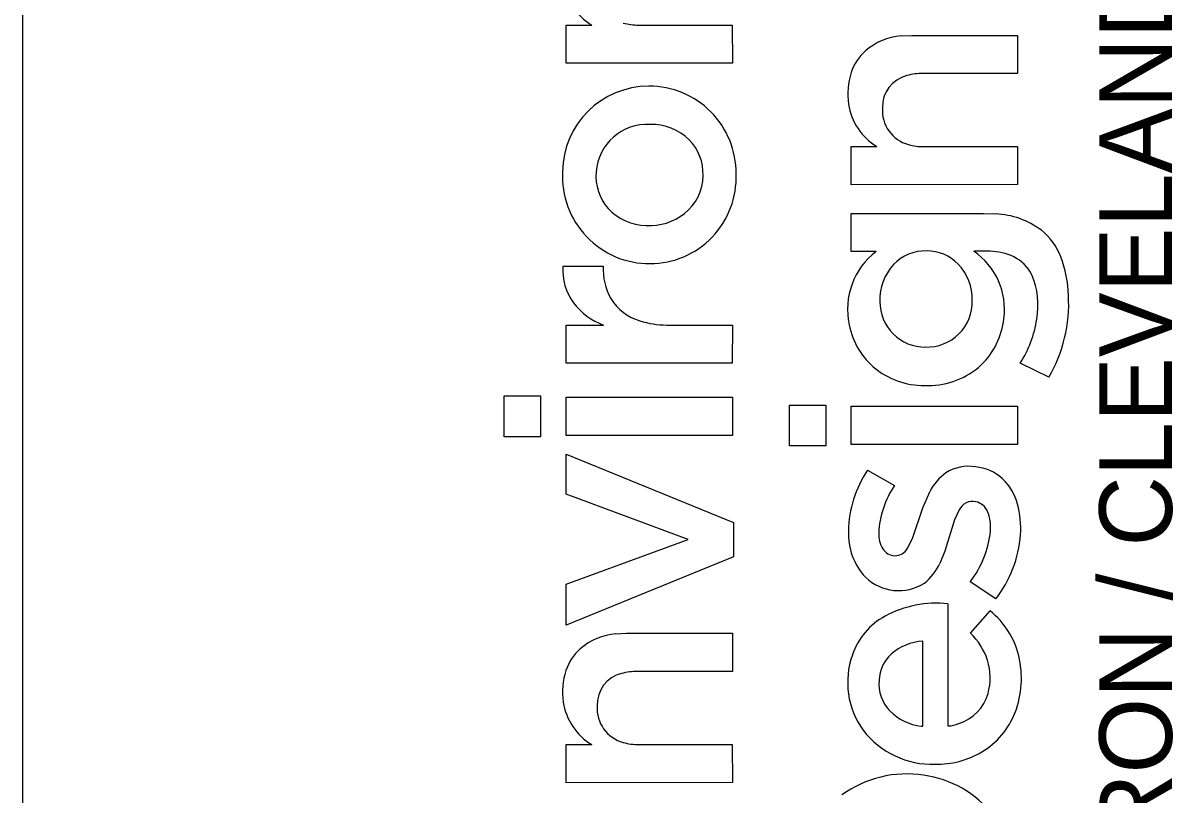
# Model space of a CAD drawing. Extents: x 0 to 34, y -1.2 to 22.
# Drawn here: x 32 to 32.901, y 3.278 to 3.882 of the extents above; entities that cross this region are included whole.
import ezdxf

# ---------------------------------------------------------------- set-up
doc = ezdxf.new("R2010")
doc.units = 0
doc.layers.add('SH_Border', color=7, linetype='Continuous')
doc.layers.add('SH_Data', color=7, linetype='Continuous')

msp = doc.modelspace()

# ---------------------------------------------------------------- linework, layer by layer
at = {"layer": 'SH_Border'}
msp.add_line((32, 0.5), (32, 21.5), dxfattribs=at)
at = {"layer": 'SH_Data'}
for p, q in [((32.42542, 3.88066), (32.44552, 3.88071)), ((32.42542, 3.85086), (32.42542, 3.88066)), ((32.48222, 3.88071), (32.55569, 3.88071)), ((32.55569, 3.88071), (32.55571, 3.85096)), ((32.68784, 3.8722), (32.69634, 3.87266)), ((32.69634, 3.87266), (32.77916, 3.87266)), ((32.77916, 3.87266), (32.77917, 3.84287)), ((32.55571, 3.85096), (32.42542, 3.85086)), ((32.77917, 3.84287), (32.70485, 3.8428)), ((32.64888, 3.7855), (32.66897, 3.78555)), ((32.64888, 3.75569), (32.64888, 3.7855)), ((32.70568, 3.78555), (32.77915, 3.78555)), ((32.77915, 3.78555), (32.77917, 3.75579)), ((32.77917, 3.75579), (32.64888, 3.75569)), ((32.6489, 3.70336), (32.64889, 3.73322)), ((32.64889, 3.73322), (32.75236, 3.73322)), ((32.75236, 3.73322), (32.76191, 3.73285)), ((32.66836, 3.70336), (32.6489, 3.70336)), ((32.75763, 3.70356), (32.74487, 3.70361)), ((32.42299, 3.69193), (32.45454, 3.69193)), ((32.42542, 3.64577), (32.45473, 3.64579)), ((32.42542, 3.61593), (32.42542, 3.64577)), ((32.50413, 3.64581), (32.55571, 3.64573)), ((32.55571, 3.64573), (32.55565, 3.61593)), ((32.55565, 3.61593), (32.42542, 3.61593)), ((32.8036, 3.60491), (32.7812, 3.61598)), ((32.37705, 3.55818), (32.37705, 3.59026)), ((32.37705, 3.59026), (32.40543, 3.59026)), ((32.40543, 3.59026), (32.40543, 3.55818)), ((32.42542, 3.55942), (32.42542, 3.58928)), ((32.42542, 3.58928), (32.55571, 3.58928)), ((32.55571, 3.58928), (32.55571, 3.55942)), ((32.60051, 3.55111), (32.60051, 3.58319)), ((32.60051, 3.58319), (32.62889, 3.58319)), ((32.62889, 3.58319), (32.62889, 3.55111)), ((32.64888, 3.55234), (32.64888, 3.5822)), ((32.64888, 3.5822), (32.77917, 3.5822)), ((32.77917, 3.5822), (32.77917, 3.55234)), ((32.55571, 3.55942), (32.42542, 3.55942)), ((32.40543, 3.55818), (32.37705, 3.55818)), ((32.62889, 3.55111), (32.60051, 3.55111)), ((32.77917, 3.55234), (32.64888, 3.55234)), ((32.42542, 3.51327), (32.42542, 3.5446)), ((32.42542, 3.5446), (32.5567, 3.4913)), ((32.66151, 3.53207), (32.68268, 3.52025)), ((32.70483, 3.50258), (32.71036, 3.51526)), ((32.52117, 3.47798), (32.42542, 3.51327)), ((32.69675, 3.47868), (32.70483, 3.50258)), ((32.73342, 3.50101), (32.72985, 3.4933)), ((32.5567, 3.4913), (32.5567, 3.46441)), ((32.72985, 3.4933), (32.72213, 3.46882)), ((32.42542, 3.44294), (32.52117, 3.47798)), ((32.69299, 3.47117), (32.69675, 3.47868)), ((32.72213, 3.46882), (32.71822, 3.45921)), ((32.5567, 3.46441), (32.42542, 3.41086)), ((32.42542, 3.41086), (32.42542, 3.44294)), ((32.76214, 3.43141), (32.74198, 3.44469)), ((32.72453, 3.42747), (32.72463, 3.33195)), ((32.74228, 3.40465), (32.75768, 3.422)), ((32.46439, 3.40397), (32.47289, 3.40443)), ((32.47289, 3.40443), (32.55571, 3.40443)), ((32.55571, 3.40443), (32.55571, 3.37465)), ((32.70489, 3.33182), (32.70489, 3.39834)), ((32.55571, 3.37465), (32.4814, 3.37457)), ((32.70361, 3.33165), (32.70489, 3.33182)), ((32.42542, 3.31728), (32.44552, 3.31733)), ((32.42542, 3.28747), (32.42542, 3.31728)), ((32.48222, 3.31733), (32.55569, 3.31733)), ((32.55569, 3.31733), (32.55571, 3.28756)), ((32.55571, 3.28756), (32.42542, 3.28747))]:
    msp.add_line(p, q, dxfattribs=at)
for points in [[(32.42542, 3.85086), (32.42542, 3.88066), (32.44552, 3.88071)], [(32.48222, 3.88071), (32.55569, 3.88071), (32.55571, 3.85096), (32.42542, 3.85086)], [(32.68784, 3.8722), (32.69634, 3.87266), (32.77916, 3.87266), (32.77917, 3.84287), (32.70485, 3.8428)], [(32.64888, 3.75569), (32.64888, 3.7855), (32.66897, 3.78555)], [(32.70568, 3.78555), (32.77915, 3.78555), (32.77917, 3.75579), (32.64888, 3.75569)], [(32.66836, 3.70336), (32.6489, 3.70336), (32.64889, 3.73322), (32.75236, 3.73322), (32.76191, 3.73285)], [(32.75763, 3.70356), (32.74487, 3.70361)], [(32.42299, 3.69193), (32.45454, 3.69193)], [(32.50413, 3.64581), (32.55571, 3.64573), (32.55565, 3.61593), (32.42542, 3.61593)], [(32.42542, 3.61593), (32.42542, 3.64577), (32.45473, 3.64579)], [(32.8036, 3.60491), (32.7812, 3.61598)], [(32.66151, 3.53207), (32.68268, 3.52025)], [(32.69299, 3.47117), (32.69675, 3.47868), (32.70483, 3.50258), (32.71036, 3.51526)], [(32.73342, 3.50101), (32.72985, 3.4933), (32.72213, 3.46882), (32.71822, 3.45921)], [(32.76214, 3.43141), (32.74198, 3.44469)], [(32.72453, 3.42747), (32.72463, 3.33195)], [(32.74228, 3.40465), (32.75768, 3.422)], [(32.46439, 3.40397), (32.47289, 3.40443), (32.55571, 3.40443), (32.55571, 3.37465), (32.4814, 3.37457)], [(32.70361, 3.33165), (32.70489, 3.33182), (32.70489, 3.39834)], [(32.42542, 3.28747), (32.42542, 3.31728), (32.44552, 3.31733)], [(32.48222, 3.31733), (32.55569, 3.31733), (32.55571, 3.28756), (32.42542, 3.28747)]]:
    msp.add_lwpolyline(points, dxfattribs=at)
for points in [[(32.37705, 3.55818), (32.37705, 3.59026), (32.40543, 3.59026), (32.40543, 3.55818)], [(32.42542, 3.55942), (32.42542, 3.58928), (32.55571, 3.58928), (32.55571, 3.55942)], [(32.60051, 3.55111), (32.60051, 3.58319), (32.62889, 3.58319), (32.62889, 3.55111)], [(32.64888, 3.55234), (32.64888, 3.5822), (32.77917, 3.5822), (32.77917, 3.55234)], [(32.42542, 3.41086), (32.42542, 3.44294), (32.52117, 3.47798), (32.42542, 3.51327), (32.42542, 3.5446), (32.5567, 3.4913), (32.5567, 3.46441)]]:
    msp.add_lwpolyline(points, close=True, dxfattribs=at)
for centre, radius, start, end in [((32.47027, 3.92141), 0.04763, 188.96462, 238.69865), ((32.47027, 3.92141), 0.04763, 188.96462, 238.69865), ((32.48183, 3.92286), 0.04215, 254.08913, 270.52838), ((32.48183, 3.92286), 0.04215, 254.08913, 270.52838), ((32.69216, 3.82251), 0.04988, 94.97056, 130.22484), ((32.69216, 3.82251), 0.04988, 94.97056, 130.22484), ((32.68694, 3.83085), 0.04016, 132.22383, 161.68229), ((32.68694, 3.83085), 0.04016, 132.22383, 161.68229), ((32.70217, 3.82642), 0.05602, 162.27398, 187.79173), ((32.70217, 3.82642), 0.05602, 162.27398, 187.79173), ((32.69828, 3.81689), 0.02498, 103.68683, 182.21395), ((32.69828, 3.81689), 0.02498, 103.68683, 182.21395), ((32.70453, 3.79679), 0.04601, 89.60515, 105.33026), ((32.70453, 3.79679), 0.04601, 89.60515, 105.33026), ((32.49014, 3.76543), 0.0674, 89.84756, 179.64047), ((32.49014, 3.76543), 0.0674, 89.84756, 179.64047), ((32.49057, 3.76474), 0.0681, 359.54009, 90.21138), ((32.49057, 3.76474), 0.0681, 359.54009, 90.21138), ((32.69372, 3.82624), 0.04763, 188.96462, 238.69865), ((32.69372, 3.82624), 0.04763, 188.96462, 238.69865), ((32.7008, 3.81381), 0.02757, 175.58441, 255.13816), ((32.7008, 3.81381), 0.02757, 175.58441, 255.13816), ((32.48923, 3.76263), 0.0404, 87.04809, 175.57259), ((32.48923, 3.76263), 0.0404, 87.04809, 175.57259), ((32.49204, 3.75999), 0.04299, 45.84264, 90.98008), ((32.49204, 3.75999), 0.04299, 45.84264, 90.98008), ((32.49458, 3.76421), 0.03821, 357.88569, 44.15902), ((32.49458, 3.76421), 0.03821, 357.88569, 44.15902), ((32.70529, 3.82769), 0.04215, 254.08913, 270.52838), ((32.70529, 3.82769), 0.04215, 254.08913, 270.52838), ((32.49083, 3.76209), 0.06819, 176.8344, 270.40384), ((32.49083, 3.76209), 0.06819, 176.8344, 270.40384), ((32.48729, 3.7625), 0.03848, 175.15378, 221.14706), ((32.48729, 3.7625), 0.03848, 175.15378, 221.14706), ((32.49123, 3.76139), 0.06749, 270.06243, 2.37759), ((32.49123, 3.76139), 0.06749, 270.06243, 2.37759), ((32.49446, 3.76318), 0.0383, 308.28936, 359.43468), ((32.49446, 3.76318), 0.0383, 308.28936, 359.43468), ((32.48919, 3.76607), 0.04228, 223.09994, 268.80895), ((32.48919, 3.76607), 0.04228, 223.09994, 268.80895), ((32.49096, 3.7679), 0.04418, 266.56515, 308.06078), ((32.49096, 3.7679), 0.04418, 266.56515, 308.06078), ((32.75907, 3.66789), 0.06503, 53.40344, 87.49062), ((32.75907, 3.66789), 0.06503, 53.40344, 87.49062), ((32.76517, 3.68039), 0.05141, 21.60748, 50.5577), ((32.76517, 3.68039), 0.05141, 21.60748, 50.5577), ((32.70292, 3.65813), 0.05692, 127.37482, 192.22468), ((32.70292, 3.65813), 0.05692, 127.37482, 192.22468), ((32.70693, 3.66927), 0.0346, 88.47302, 136.42562), ((32.70693, 3.66927), 0.0346, 88.47302, 136.42562), ((32.70814, 3.66963), 0.03424, 44.27195, 90.47623), ((32.70814, 3.66963), 0.03424, 44.27195, 90.47623), ((32.71421, 3.65829), 0.05472, 352.1125, 55.92295), ((32.71421, 3.65829), 0.05472, 352.1125, 55.92295), ((32.75666, 3.65725), 0.04633, 65.01687, 88.8011), ((32.75666, 3.65725), 0.04633, 65.01687, 88.8011), ((32.7626, 3.67155), 0.03085, 26.26808, 63.80301), ((32.7626, 3.67155), 0.03085, 26.26808, 63.80301), ((32.73069, 3.66714), 0.08835, 1.15143, 21.3627), ((32.73069, 3.66714), 0.08835, 1.15143, 21.3627), ((32.46616, 3.68882), 0.04329, 175.87313, 216.34747), ((32.46616, 3.68882), 0.04329, 175.87313, 216.34747), ((32.50087, 3.68948), 0.04639, 176.9688, 209.60636), ((32.50087, 3.68948), 0.04639, 176.9688, 209.60636), ((32.71141, 3.66602), 0.0401, 137.46739, 182.33237), ((32.71141, 3.66602), 0.0401, 137.46739, 182.33237), ((32.70368, 3.666), 0.03996, 358.57141, 43.53765), ((32.70368, 3.666), 0.03996, 358.57141, 43.53765), ((32.73565, 3.66154), 0.05953, 349.30734, 23.43071), ((32.73565, 3.66154), 0.05953, 349.30734, 23.43071), ((32.70538, 3.66244), 0.11383, 329.6388, 3.25998), ((32.70538, 3.66244), 0.11383, 329.6388, 3.25998), ((32.47466, 3.69716), 0.05511, 218.09809, 248.7907), ((32.47466, 3.69716), 0.05511, 218.09809, 248.7907), ((32.49514, 3.68814), 0.04079, 211.94466, 253.2028), ((32.49514, 3.68814), 0.04079, 211.94466, 253.2028), ((32.70645, 3.6637), 0.03511, 178.88208, 271.08374), ((32.70645, 3.6637), 0.03511, 178.88208, 271.08374), ((32.70818, 3.66404), 0.03546, 268.27882, 1.55016), ((32.70818, 3.66404), 0.03546, 268.27882, 1.55016), ((32.50465, 3.7165), 0.07069, 252.46555, 269.57296), ((32.50465, 3.7165), 0.07069, 252.46555, 269.57296), ((32.70988, 3.65708), 0.05887, 313.74196, 353.8554), ((32.70988, 3.65708), 0.05887, 313.74196, 353.8554), ((32.70738, 3.66334), 0.08771, 327.31495, 351.57478), ((32.70738, 3.66334), 0.08771, 327.31495, 351.57478), ((32.70463, 3.65696), 0.05837, 190.75182, 231.28919), ((32.70463, 3.65696), 0.05837, 190.75182, 231.28919), ((32.70954, 3.65901), 0.06051, 269.6361, 312.70877), ((32.70954, 3.65901), 0.06051, 269.6361, 312.70877), ((32.70632, 3.66112), 0.06269, 232.46061, 272.59022), ((32.70632, 3.66112), 0.06269, 232.46061, 272.59022), ((32.73636, 3.48258), 0.08973, 146.53104, 178.7571), ((32.73636, 3.48258), 0.08973, 146.53104, 178.7571), ((32.7406, 3.5026), 0.03263, 80.17192, 122.51969), ((32.7406, 3.5026), 0.03263, 80.17192, 122.51969), ((32.74278, 3.49824), 0.03667, 47.79344, 84.68918), ((32.74278, 3.49824), 0.03667, 47.79344, 84.68918), ((32.74661, 3.49713), 0.04053, 125.51182, 153.41595), ((32.74661, 3.49713), 0.04053, 125.51182, 153.41595), ((32.73788, 3.4946), 0.04267, 14.9966, 46.20632), ((32.73788, 3.4946), 0.04267, 14.9966, 46.20632), ((32.74519, 3.4789), 0.07495, 146.51121, 176.91007), ((32.74519, 3.4789), 0.07495, 146.51121, 176.91007), ((32.74384, 3.49631), 0.01143, 76.66094, 155.7053), ((32.74384, 3.49631), 0.01143, 76.66094, 155.7053), ((32.74397, 3.49511), 0.01256, 21.5098, 78.52618), ((32.74397, 3.49511), 0.01256, 21.5098, 78.52618), ((32.71044, 3.48674), 0.07121, 355.83062, 15.39138), ((32.71044, 3.48674), 0.07121, 355.83062, 15.39138), ((32.72592, 3.48766), 0.03209, 354.57264, 22.06805), ((32.72592, 3.48766), 0.03209, 354.57264, 22.06805), ((32.69666, 3.48238), 0.05005, 177.53659, 222.79318), ((32.69666, 3.48238), 0.05005, 177.53659, 222.79318), ((32.6931, 3.48233), 0.02276, 178.47474, 211.08679), ((32.6931, 3.48233), 0.02276, 178.47474, 211.08679), ((32.68248, 3.49149), 0.0757, 321.81101, 354.79685), ((32.68248, 3.49149), 0.0757, 321.81101, 354.79685), ((32.68952, 3.4882), 0.09219, 321.9777, 355.87384), ((32.68952, 3.4882), 0.09219, 321.9777, 355.87384), ((32.68331, 3.4767), 0.01148, 212.23676, 268.37769), ((32.68331, 3.4767), 0.01148, 212.23676, 268.37769), ((32.68342, 3.47589), 0.01067, 267.71603, 333.73375), ((32.68342, 3.47589), 0.01067, 267.71603, 333.73375), ((32.68098, 3.4758), 0.04077, 308.08772, 335.98736), ((32.68098, 3.4758), 0.04077, 308.08772, 335.98736), ((32.68599, 3.47535), 0.0375, 225.98539, 302.47965), ((32.68599, 3.47535), 0.0375, 225.98539, 302.47965), ((32.7152, 3.34414), 0.08384, 83.61499, 118.28755), ((32.7152, 3.34414), 0.08384, 83.61499, 118.28755), ((32.70239, 3.36906), 0.05583, 118.83082, 160.62438), ((32.70239, 3.36906), 0.05583, 118.83082, 160.62438), ((32.71744, 3.37167), 0.06443, 13.53365, 51.36148), ((32.71744, 3.37167), 0.06443, 13.53365, 51.36148), ((32.46871, 3.35428), 0.04988, 94.96958, 130.22249), ((32.46871, 3.35428), 0.04988, 94.96958, 130.22249), ((32.70785, 3.35609), 0.04235, 94.00805, 130.88169), ((32.70785, 3.35609), 0.04235, 94.00805, 130.88169), ((32.70378, 3.36556), 0.05486, 19.03571, 45.44059), ((32.70378, 3.36556), 0.05486, 19.03571, 45.44059), ((32.46348, 3.36263), 0.04015, 132.22192, 161.68183), ((32.46348, 3.36263), 0.04015, 132.22192, 161.68183), ((32.71041, 3.36612), 0.06437, 160.52012, 215.78311), ((32.71041, 3.36612), 0.06437, 160.52012, 215.78311), ((32.70048, 3.36628), 0.02985, 132.98507, 177.179), ((32.70048, 3.36628), 0.02985, 132.98507, 177.179), ((32.71069, 3.3697), 0.047, 344.60586, 17.007), ((32.71069, 3.3697), 0.047, 344.60586, 17.007), ((32.70635, 3.36921), 0.07579, 339.3542, 13.37853), ((32.70635, 3.36921), 0.07579, 339.3542, 13.37853), ((32.47872, 3.35819), 0.05601, 162.27355, 187.79185), ((32.47872, 3.35819), 0.05601, 162.27355, 187.79185), ((32.47482, 3.34867), 0.02498, 103.68646, 182.21874), ((32.47482, 3.34867), 0.02498, 103.68646, 182.21874), ((32.48108, 3.32856), 0.04601, 89.60494, 105.3284), ((32.48108, 3.32856), 0.04601, 89.60494, 105.3284), ((32.7017, 3.36503), 0.03115, 175.00126, 223.28301), ((32.7017, 3.36503), 0.03115, 175.00126, 223.28301), ((32.7224, 3.36715), 0.03504, 288.00773, 343.55078), ((32.7224, 3.36715), 0.03504, 288.00773, 343.55078), ((32.47026, 3.35802), 0.04762, 188.96199, 238.70369), ((32.47026, 3.35802), 0.04762, 188.96199, 238.70369), ((32.47735, 3.34558), 0.02756, 175.58538, 255.14386), ((32.47735, 3.34558), 0.02756, 175.58538, 255.14386), ((32.70891, 3.37363), 0.04231, 225.06188, 262.79738), ((32.70891, 3.37363), 0.04231, 225.06188, 262.79738), ((32.71894, 3.3652), 0.0626, 300.94269, 338.73225), ((32.71894, 3.3652), 0.0626, 300.94269, 338.73225), ((32.72474, 3.35216), 0.02021, 269.7003, 294.8711), ((32.72474, 3.35216), 0.02021, 269.7003, 294.8711), ((32.71253, 3.37054), 0.06872, 217.74516, 271.65431), ((32.71253, 3.37054), 0.06872, 217.74516, 271.65431), ((32.48183, 3.35948), 0.04215, 254.09162, 270.52835), ((32.48183, 3.35948), 0.04215, 254.09162, 270.52835), ((32.71549, 3.37241), 0.07056, 269.20477, 300.33412), ((32.71549, 3.37241), 0.07056, 269.20477, 300.33412), ((32.69229, 3.20792), 0.08641, 81.19402, 125.99844), ((32.69229, 3.20792), 0.08641, 81.19402, 125.99844), ((32.69458, 3.21132), 0.08272, 37.85208, 82.40204), ((32.69458, 3.21132), 0.08272, 37.85208, 82.40204)]:
    msp.add_arc(centre, radius, start, end, dxfattribs=at)

# ---------------------------------------------------------------- texts
msp.add_text('AKRON / CLEVELAND / COLUMBUS', height=0.056969, rotation=90, dxfattribs=at).set_placement((32.90012, 3.138))

doc.saveas('drawing.dxf')
